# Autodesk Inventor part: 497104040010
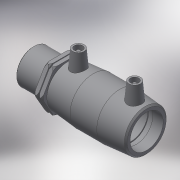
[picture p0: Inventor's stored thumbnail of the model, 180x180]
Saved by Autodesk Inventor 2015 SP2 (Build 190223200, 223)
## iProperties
Created: 2017-06
Part Number: 497104040010
Material: Generic
Description: PLASSON PE MALE TRANSITION COUPLER 40-1"
Document SubType Name: Modeling
Designer: KIM
Mass: 55.0731 g
Surface Area: 148.067 cm^2
Volume: 55.0731 cm^3
Density: 1 g/cm^3
Appearance: Default
Author: KIM
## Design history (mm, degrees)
derived "497104.ipt"
feature "Solid1::497104.ipt"
tag "TaggingFeature1"
body "Solid1"
other parameters: "d0" = 97, "d2" = 56, "d3" = 47, "d4" = 32.33333, "d5" = 50.4, "d6" = 38, "d8" = 168 deg, "d10" = 18.8, "d11" = 6.26667, "d29" = 46, "d30" = 14, "d31" = 33.95, "d34" = 5 deg, "d41" = 4, "d42" = 14, "d43" = 0, "d48" = 3, "d49" = 0, "d58" = 33.249, "d59" = 26.5992, "d60" = 33.3, "d61" = 46.5486, "d62" = 0.66498, "d65" = 1.68, "d70" = 0.1, "d71" = 37, "d72" = 9.25, "d73" = 18.8, "d75" = 0, "d76" = 0.925, "d77" = 4.1625, "d78" = 46.5486, "L_" = 134, "L_2" = 47, "D_1" = 56, "A_" = 46, "d_2" = 12, "L_1" = 37, "R_" = 33.249
